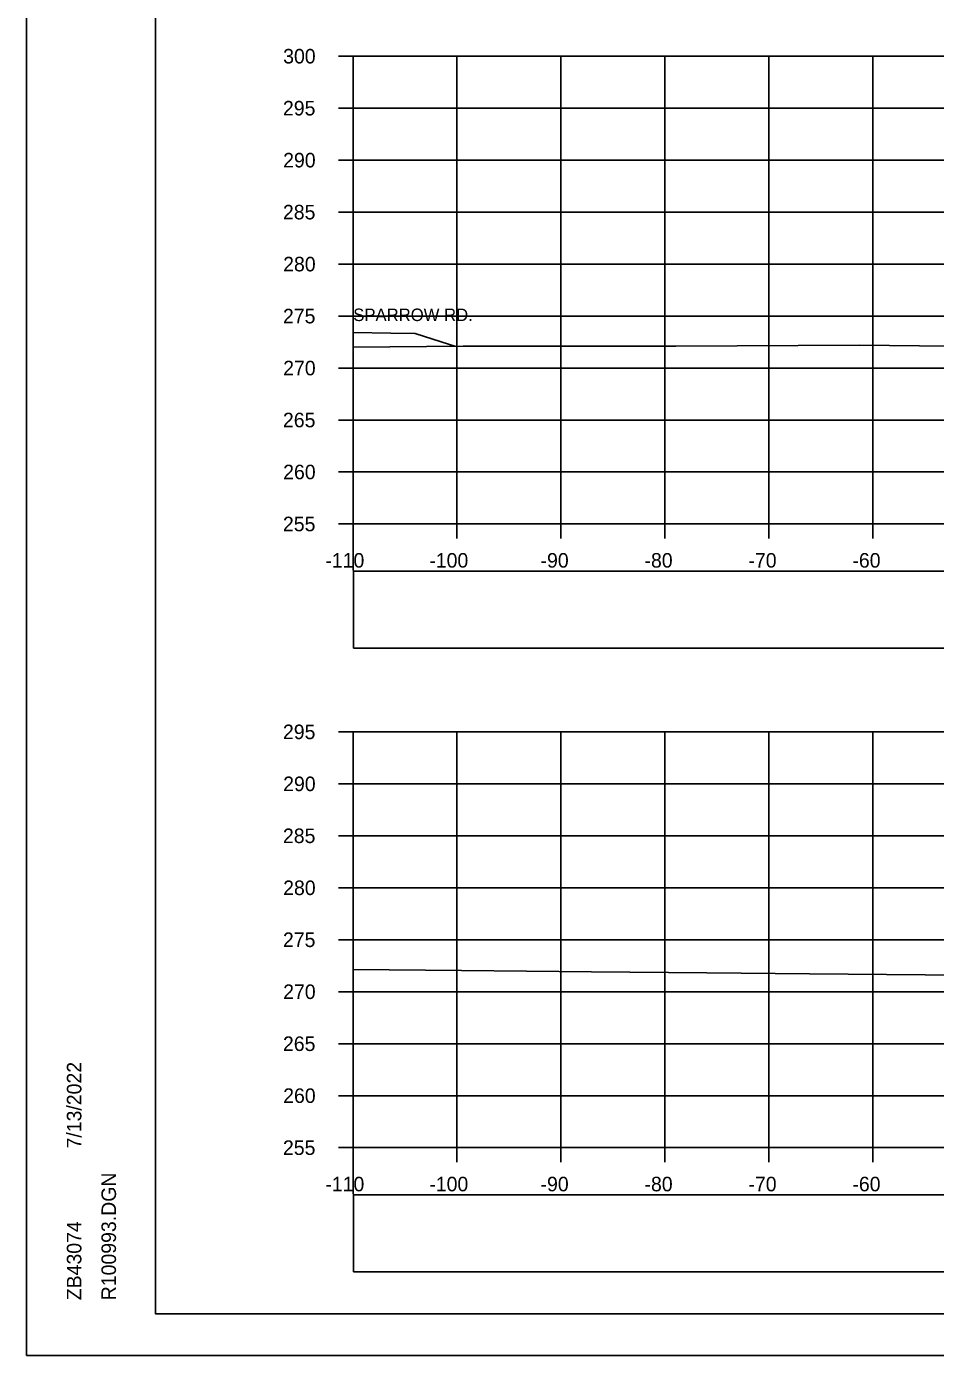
# Model space of a CAD drawing. Extents: x 4667 to 1632277, y -2100 to 724501.
# Drawn here: x 5635.8 to 5723.2, y -683.7 to -555.9 of the extents above; entities that cross this region are included whole.
import ezdxf

# ---------------------------------------------------------------- set-up
doc = ezdxf.new("R2010")
doc.units = 0
for name, color, linetype in [('R_Axis', 7, 'Continuous'), ('R_Axis Annot', 7, 'Continuous'), ('R_Border', 7, 'Continuous'), ('R_Drive', 7, 'Continuous'), ('R_Exist Surface', 7, 'Continuous'), ('R_Grid', 7, 'Continuous'), ('R_No Plot', 7, 'Continuous'), ('R_Proposed CofA', 7, 'Continuous')]:
    doc.layers.add(name, color=color, linetype=linetype)

msp = doc.modelspace()

# ---------------------------------------------------------------- linework, layer by layer
at = {"layer": 'R_Axis'}
for p, q in [((5665.78, -558.75), (5667.18, -558.75)), ((5667.18, -603.75), (5667.18, -558.75)), ((5665.78, -563.75), (5667.18, -563.75)), ((5665.78, -568.75), (5667.18, -568.75)), ((5665.78, -573.75), (5667.18, -573.75)), ((5665.78, -578.75), (5667.18, -578.75)), ((5665.78, -583.75), (5667.18, -583.75)), ((5665.78, -588.75), (5667.18, -588.75)), ((5665.78, -593.75), (5667.18, -593.75)), ((5665.78, -598.75), (5667.18, -598.75)), ((5665.78, -603.75), (5667.18, -603.75)), ((5667.18, -603.75), (5947.18, -603.75)), ((5667.18, -605.15), (5667.18, -603.75)), ((5677.18, -605.15), (5677.18, -603.75)), ((5687.18, -605.15), (5687.18, -603.75)), ((5697.18, -605.15), (5697.18, -603.75)), ((5707.18, -605.15), (5707.18, -603.75)), ((5717.18, -605.15), (5717.18, -603.75)), ((5665.78, -623.75), (5667.18, -623.75)), ((5667.18, -663.75), (5667.18, -623.75)), ((5665.78, -628.75), (5667.18, -628.75)), ((5665.78, -633.75), (5667.18, -633.75)), ((5665.78, -638.75), (5667.18, -638.75)), ((5665.78, -643.75), (5667.18, -643.75)), ((5665.78, -648.75), (5667.18, -648.75)), ((5665.78, -653.75), (5667.18, -653.75)), ((5665.78, -658.75), (5667.18, -658.75)), ((5665.78, -663.75), (5667.18, -663.75)), ((5667.18, -663.75), (5947.18, -663.75)), ((5667.18, -665.15), (5667.18, -663.75)), ((5677.18, -665.15), (5677.18, -663.75)), ((5687.18, -665.15), (5687.18, -663.75)), ((5697.18, -665.15), (5697.18, -663.75)), ((5707.18, -665.15), (5707.18, -663.75)), ((5717.18, -665.15), (5717.18, -663.75))]:
    msp.add_line(p, q, dxfattribs=at)
at = {"layer": 'R_Border'}
for p, q in [((5648.18, -679.75), (5648.18, -474.29)), ((5648.18, -679.75), (5648.18, -679.75)), ((5964.36, -679.75), (5648.18, -679.75))]:
    msp.add_line(p, q, dxfattribs=at)
at = {"layer": 'R_Drive'}
msp.add_lwpolyline([(5667.18, -585.34), (5670.81, -585.4), (5673.16, -585.43), (5676.45, -586.49), (5676.98, -586.66)], dxfattribs=at)
at = {"layer": 'R_Exist Surface'}
for points in [[(5667.18, -586.73), (5677.76, -586.65), (5698.24, -586.65), (5715.89, -586.56), (5730.3, -586.71), (5743.13, -586.96), (5751.19, -587.07), (5770.1, -587.39), (5789.82, -587.57), (5792.47, -587.59), (5812.28, -587.45), (5826.84, -587.36), (5835.07, -587.3), (5846.16, -587.24)], [(5667.18, -646.62), (5677.62, -646.71), (5690.13, -646.83), (5701.21, -646.93), (5711.1, -647.02), (5729.62, -647.18), (5739.45, -647.22), (5748.81, -647.25), (5776.06, -647.55), (5798.09, -647.78), (5846.08, -647.27)]]:
    msp.add_lwpolyline(points, dxfattribs=at)
at = {"layer": 'R_Grid'}
for p, q in [((5667.18, -558.75), (5947.18, -558.75)), ((5667.18, -603.75), (5667.18, -558.75)), ((5677.18, -603.75), (5677.18, -558.75)), ((5687.18, -603.75), (5687.18, -558.75)), ((5697.18, -603.75), (5697.18, -558.75)), ((5707.18, -603.75), (5707.18, -558.75)), ((5717.18, -603.75), (5717.18, -558.75)), ((5667.18, -563.75), (5947.18, -563.75)), ((5667.18, -568.75), (5947.18, -568.75)), ((5667.18, -573.75), (5947.18, -573.75)), ((5667.18, -578.75), (5947.18, -578.75)), ((5667.18, -583.75), (5947.18, -583.75)), ((5667.18, -588.75), (5947.18, -588.75)), ((5667.18, -593.75), (5947.18, -593.75)), ((5667.18, -598.75), (5947.18, -598.75)), ((5667.18, -603.75), (5947.18, -603.75)), ((5667.18, -623.75), (5947.18, -623.75)), ((5667.18, -663.75), (5667.18, -623.75)), ((5677.18, -663.75), (5677.18, -623.75)), ((5687.18, -663.75), (5687.18, -623.75)), ((5697.18, -663.75), (5697.18, -623.75)), ((5707.18, -663.75), (5707.18, -623.75)), ((5717.18, -663.75), (5717.18, -623.75)), ((5667.18, -628.75), (5947.18, -628.75)), ((5667.18, -633.75), (5947.18, -633.75)), ((5667.18, -638.75), (5947.18, -638.75)), ((5667.18, -643.75), (5947.18, -643.75)), ((5667.18, -648.75), (5947.18, -648.75)), ((5667.18, -653.75), (5947.18, -653.75)), ((5667.18, -658.75), (5947.18, -658.75)), ((5667.18, -663.75), (5947.18, -663.75))]:
    msp.add_line(p, q, dxfattribs=at)
at = {"layer": 'R_No Plot'}
for p, q in [((5667.18, -605.15), (5667.18, -608.23)), ((5667.18, -665.15), (5667.18, -668.23)), ((5635.78, -683.73), (5969.12, -683.73))]:
    msp.add_line(p, q, dxfattribs=at)
for points in [[(5635.78, -470.4), (5969.12, -470.4), (5969.12, -683.74), (5635.78, -683.74)], [(5882.1, -474.29), (5901.72, -474.29), (5901.72, -484.17), (5917.84, -484.17), (5941.04, -484.17), (5941.04, -508.51), (5964.36, -508.51), (5964.36, -679.75), (5648.18, -679.75), (5648.18, -474.29)]]:
    msp.add_lwpolyline(points, close=True, dxfattribs=at)
at = {"layer": 'R_Proposed CofA'}
for points in [[(5667.23, -615.7), (5947.13, -615.7), (5947.13, -608.28), (5667.23, -608.28)], [(5667.23, -675.7), (5947.13, -675.7), (5947.13, -668.28), (5667.23, -668.28)]]:
    msp.add_lwpolyline(points, close=True, dxfattribs=at)

# ---------------------------------------------------------------- texts
at = {"layer": 'R_Axis Annot'}
for s, p in [('300', (5660.46, -559.45)), ('295', (5660.44, -564.45)), ('290', (5660.46, -569.45)), ('285', (5660.44, -574.45)), ('280', (5660.46, -579.45)), ('275', (5660.44, -584.45)), ('270', (5660.46, -589.45)), ('265', (5660.44, -594.45)), ('260', (5660.46, -599.45)), ('255', (5660.44, -604.45)), ('-110', (5664.52, -607.95)), ('-100', (5674.52, -607.95)), ('-90', (5685.22, -607.95)), ('-80', (5695.22, -607.95)), ('-70', (5705.22, -607.95)), ('-60', (5715.22, -607.95)), ('295', (5660.44, -624.45)), ('290', (5660.46, -629.45)), ('285', (5660.44, -634.45)), ('280', (5660.46, -639.45)), ('275', (5660.44, -644.45)), ('270', (5660.46, -649.45)), ('265', (5660.44, -654.45)), ('260', (5660.46, -659.45)), ('255', (5660.44, -664.45)), ('-110', (5664.52, -667.95)), ('-100', (5674.52, -667.95)), ('-90', (5685.22, -667.95)), ('-80', (5695.22, -667.95)), ('-70', (5705.22, -667.95)), ('-60', (5715.22, -667.95))]:
    msp.add_text(s, height=1.4, dxfattribs=at).set_placement(p)
at = {"layer": 'R_Border'}
for s, p in [('7/13/2022', (5641.05, -663.83)), ('R100993.DGN', (5644.38, -678.43)), ('ZB43074', (5641.05, -678.43))]:
    msp.add_text(s, height=1.4, rotation=90, dxfattribs=at).set_placement(p)
at = {"layer": 'R_Drive'}
msp.add_text('SPARROW RD.', height=1.2, dxfattribs=at).set_placement((5667.2, -584.23))

doc.saveas('drawing.dxf')
